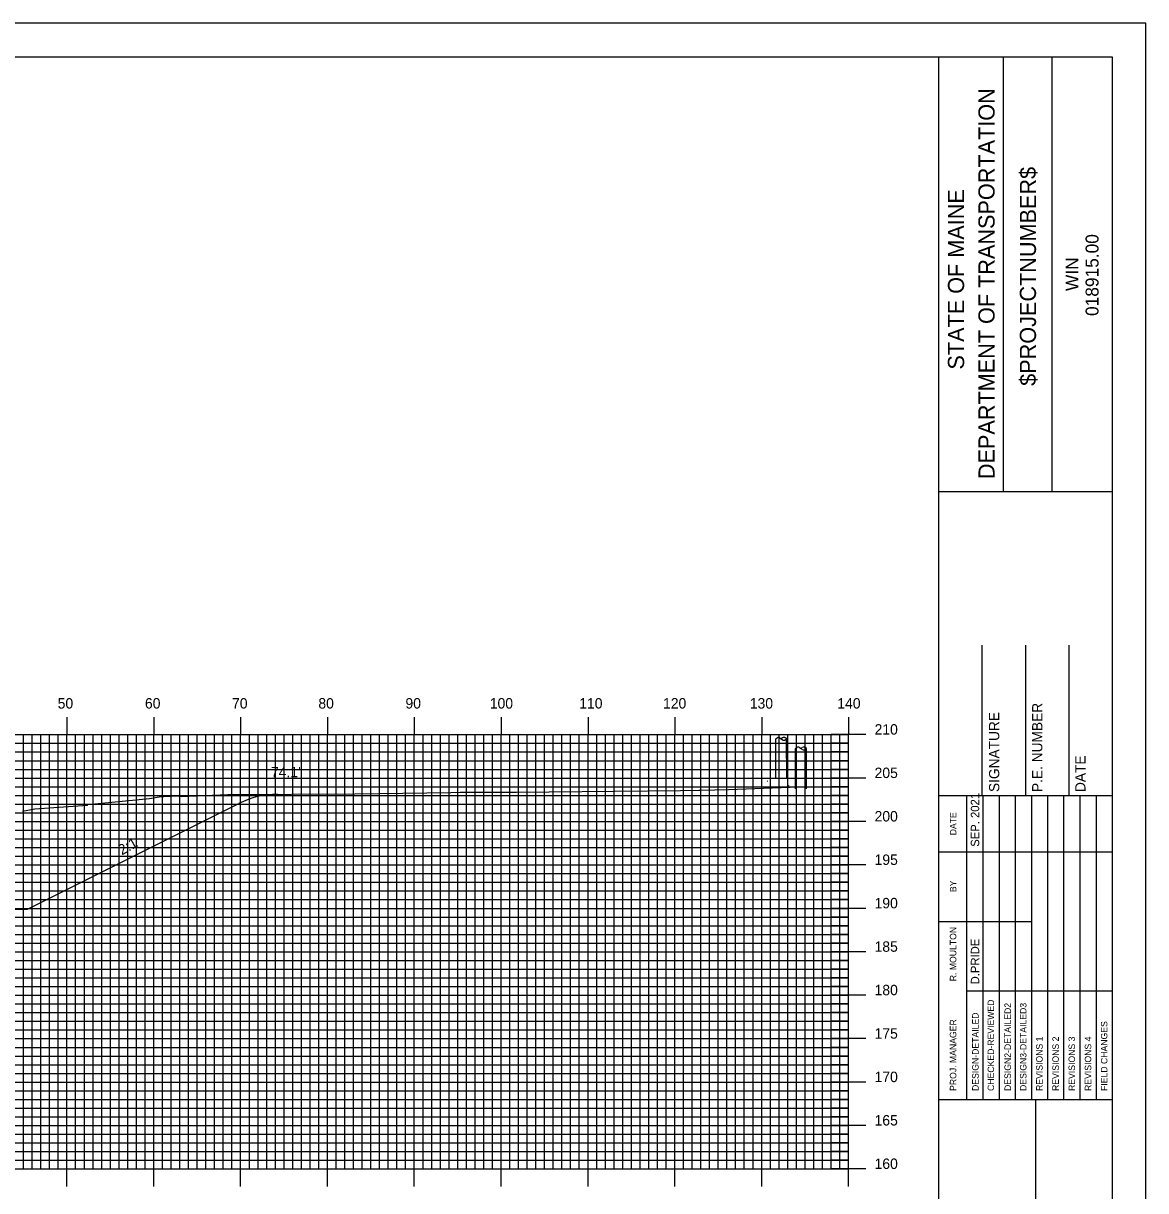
# Model space of a CAD drawing. Extents: x 1794846 to 1795189, y 442591 to 442811.
# Drawn here: x 1795056.8 to 1795186.1, y 442676.2 to 442810.5 of the extents above; entities that cross this region are included whole.
import ezdxf

# ---------------------------------------------------------------- set-up
doc = ezdxf.new("R2010")
doc.units = 0
for name, color, linetype in [('ANNOTATION', 7, 'Continuous'), ('BORDER', 7, 'Continuous'), ('D_Roadway_Centerline', 7, 'Continuous'), ('D_Text_Standard', 7, 'Continuous'), ('H_V ANNOTATION', 7, 'Continuous'), ('M_Utilities_Pole', 7, 'Continuous'), ('MAJOR', 7, 'Continuous'), ('MINOR', 7, 'Continuous'), ('PLOT BOUNDARY', 7, 'Continuous'), ('S_Roadway_Centerline', 7, 'Continuous'), ('S_Utilities_Pole_Power', 7, 'Continuous')]:
    doc.layers.add(name, color=color, linetype=linetype)

msp = doc.modelspace()

# ---------------------------------------------------------------- linework, layer by layer
at = {"layer": 'BORDER'}
for p, q in [((1795162.25, 442596.67), (1795162.25, 442806.67)), ((1795169.71, 442756.66), (1795169.71, 442806.66)), ((1795175.3, 442756.66), (1795175.3, 442806.66)), ((1795162.25, 442756.65), (1795182.25, 442756.65)), ((1795167.25, 442721.67), (1795167.25, 442738.97)), ((1795172.25, 442721.67), (1795172.25, 442738.97)), ((1795177.25, 442721.67), (1795177.25, 442738.97)), ((1795162.25, 442721.67), (1795182.25, 442721.67)), ((1795162.25, 442686.67), (1795182.25, 442686.67)), ((1795173.43, 442616.67), (1795173.43, 442686.67))]:
    msp.add_line(p, q, dxfattribs=at)
msp.add_lwpolyline([(1794862.25, 442596.67), (1795182.25, 442596.67), (1795182.25, 442806.67), (1794862.25, 442806.67)], close=True, dxfattribs=at)
for points in [[(1795165.48, 442715.17), (1795165.48, 442721.67)], [(1795167.35, 442686.68), (1795167.35, 442721.67)], [(1795169.21, 442721.67), (1795169.21, 442686.68)], [(1795171.07, 442686.68), (1795171.07, 442721.67)], [(1795172.94, 442686.68), (1795172.94, 442721.67)], [(1795174.8, 442686.68), (1795174.8, 442721.67)], [(1795176.66, 442686.68), (1795176.66, 442721.67)], [(1795178.53, 442686.68), (1795178.53, 442721.67)], [(1795180.39, 442686.68), (1795180.39, 442721.67)], [(1795165.48, 442686.68), (1795165.48, 442720.26)], [(1795162.25, 442715.17), (1795182.25, 442715.17)], [(1795162.25, 442707.17), (1795165.48, 442707.17)], [(1795165.48, 442707.17), (1795172.94, 442707.17)], [(1795165.48, 442699.17), (1795182.25, 442699.17)]]:
    msp.add_lwpolyline(points, dxfattribs=at)
at = {"layer": 'D_Roadway_Centerline'}
msp.add_lwpolyline([(1794974.71, 442699.87), (1794977.68, 442688), (1794981.68, 442689), (1794991.85, 442691.55), (1794999.85, 442691.87), (1795011.85, 442691.63), (1795023.85, 442691.39), (1795031.85, 442691.07), (1795042.03, 442688.52), (1795046.03, 442687.52), (1795051.29, 442708.57), (1795057.29, 442708.57), (1795081.65, 442720.74)], dxfattribs=at)
msp.add_arc((1795086.12, 442711.8), 10, 90.2277, 116.5651, dxfattribs=at)
at = {"layer": 'M_Utilities_Pole'}
for p, q in [((1795142.54, 442723.32), (1795142.54, 442723.3)), ((1795144.92, 442722.8), (1795144.92, 442722.78))]:
    msp.add_line(p, q, dxfattribs=at)
for centre in [(1795142.54, 442723.31), (1795144.92, 442722.79)]:
    msp.add_circle(centre, 0.00417, dxfattribs=at)
at = {"layer": 'MAJOR'}
for p, q in [((1795061.85, 442730.67), (1795061.85, 442728.67)), ((1795071.85, 442730.67), (1795071.85, 442728.67)), ((1795081.85, 442730.67), (1795081.85, 442728.67)), ((1795091.85, 442730.67), (1795091.85, 442728.67)), ((1795101.85, 442730.67), (1795101.85, 442728.67)), ((1795111.85, 442730.67), (1795111.85, 442728.67)), ((1795121.85, 442730.67), (1795121.85, 442728.67)), ((1795131.85, 442730.67), (1795131.85, 442728.67)), ((1795141.85, 442730.67), (1795141.85, 442728.67)), ((1795151.85, 442730.67), (1795151.85, 442728.67)), ((1794871.85, 442728.67), (1795151.85, 442728.67)), ((1794871.85, 442728.67), (1795151.85, 442728.67)), ((1795061.85, 442678.67), (1795061.85, 442728.67)), ((1795071.85, 442678.67), (1795071.85, 442728.67)), ((1795081.85, 442678.67), (1795081.85, 442728.67)), ((1795091.85, 442678.67), (1795091.85, 442728.67)), ((1795101.85, 442678.67), (1795101.85, 442728.67)), ((1795111.85, 442678.67), (1795111.85, 442728.67)), ((1795121.85, 442678.67), (1795121.85, 442728.67)), ((1795131.85, 442678.67), (1795131.85, 442728.67)), ((1795141.85, 442678.67), (1795141.85, 442728.67)), ((1795153.86, 442728.67), (1795149.85, 442728.67)), ((1795151.85, 442678.67), (1795151.85, 442728.67)), ((1795151.85, 442678.67), (1795151.85, 442728.67)), ((1794871.85, 442723.67), (1795151.85, 442723.67)), ((1795153.86, 442723.67), (1795149.85, 442723.67)), ((1794871.85, 442718.67), (1795151.85, 442718.67)), ((1795153.86, 442718.67), (1795149.85, 442718.67)), ((1794871.85, 442713.67), (1795151.85, 442713.67)), ((1795153.86, 442713.67), (1795149.85, 442713.67)), ((1794871.85, 442708.67), (1795151.85, 442708.67)), ((1795153.86, 442708.67), (1795149.85, 442708.67)), ((1794871.85, 442703.67), (1795151.85, 442703.67)), ((1795153.86, 442703.67), (1795149.85, 442703.67)), ((1794871.85, 442698.67), (1795151.85, 442698.67)), ((1795153.86, 442698.67), (1795149.85, 442698.67)), ((1794871.85, 442693.67), (1795151.85, 442693.67)), ((1795153.86, 442693.67), (1795149.85, 442693.67)), ((1794871.85, 442688.67), (1795151.85, 442688.67)), ((1795153.86, 442688.67), (1795149.85, 442688.67)), ((1794871.85, 442683.67), (1795151.85, 442683.67)), ((1795153.86, 442683.67), (1795149.85, 442683.67)), ((1794871.85, 442678.67), (1795151.85, 442678.67)), ((1794871.85, 442678.67), (1795151.85, 442678.67)), ((1795061.85, 442676.66), (1795061.85, 442678.67)), ((1795071.85, 442676.66), (1795071.85, 442678.67)), ((1795081.85, 442676.66), (1795081.85, 442678.67)), ((1795091.85, 442676.66), (1795091.85, 442678.67)), ((1795101.85, 442676.66), (1795101.85, 442678.67)), ((1795111.85, 442676.66), (1795111.85, 442678.67)), ((1795121.85, 442676.66), (1795121.85, 442678.67)), ((1795131.85, 442676.66), (1795131.85, 442678.67)), ((1795141.85, 442676.66), (1795141.85, 442678.67)), ((1795153.86, 442678.67), (1795149.85, 442678.67)), ((1795151.85, 442676.66), (1795151.85, 442678.67))]:
    msp.add_line(p, q, dxfattribs=at)
at = {"layer": 'MINOR'}
for p, q in [((1795056.85, 442678.67), (1795056.85, 442728.67)), ((1795057.85, 442678.67), (1795057.85, 442728.67)), ((1795058.85, 442678.67), (1795058.85, 442728.67)), ((1795059.85, 442678.67), (1795059.85, 442728.67)), ((1795060.85, 442678.67), (1795060.85, 442728.67)), ((1795062.85, 442678.67), (1795062.85, 442728.67)), ((1795063.85, 442678.67), (1795063.85, 442728.67)), ((1795064.85, 442678.67), (1795064.85, 442728.67)), ((1795065.85, 442678.67), (1795065.85, 442728.67)), ((1795066.85, 442678.67), (1795066.85, 442728.67)), ((1795067.85, 442678.67), (1795067.85, 442728.67)), ((1795068.85, 442678.67), (1795068.85, 442728.67)), ((1795069.85, 442678.67), (1795069.85, 442728.67)), ((1795070.85, 442678.67), (1795070.85, 442728.67)), ((1795072.85, 442678.67), (1795072.85, 442728.67)), ((1795073.85, 442678.67), (1795073.85, 442728.67)), ((1795074.85, 442678.67), (1795074.85, 442728.67)), ((1795075.85, 442678.67), (1795075.85, 442728.67)), ((1795076.85, 442678.67), (1795076.85, 442728.67)), ((1795077.85, 442678.67), (1795077.85, 442728.67)), ((1795078.85, 442678.67), (1795078.85, 442728.67)), ((1795079.85, 442678.67), (1795079.85, 442728.67)), ((1795080.85, 442678.67), (1795080.85, 442728.67)), ((1795082.85, 442678.67), (1795082.85, 442728.67)), ((1795083.85, 442678.67), (1795083.85, 442728.67)), ((1795084.85, 442678.67), (1795084.85, 442728.67)), ((1795085.85, 442678.67), (1795085.85, 442728.67)), ((1795086.85, 442678.67), (1795086.85, 442728.67)), ((1795087.85, 442678.67), (1795087.85, 442728.67)), ((1795088.85, 442678.67), (1795088.85, 442728.67)), ((1795089.85, 442678.67), (1795089.85, 442728.67)), ((1795090.85, 442678.67), (1795090.85, 442728.67)), ((1795092.85, 442678.67), (1795092.85, 442728.67)), ((1795093.85, 442678.67), (1795093.85, 442728.67)), ((1795094.85, 442678.67), (1795094.85, 442728.67)), ((1795095.85, 442678.67), (1795095.85, 442728.67)), ((1795096.85, 442678.67), (1795096.85, 442728.67)), ((1795097.85, 442678.67), (1795097.85, 442728.67)), ((1795098.85, 442678.67), (1795098.85, 442728.67)), ((1795099.85, 442678.67), (1795099.85, 442728.67)), ((1795100.85, 442678.67), (1795100.85, 442728.67)), ((1795102.85, 442678.67), (1795102.85, 442728.67)), ((1795103.85, 442678.67), (1795103.85, 442728.67)), ((1795104.85, 442678.67), (1795104.85, 442728.67)), ((1795105.85, 442678.67), (1795105.85, 442728.67)), ((1795106.85, 442678.67), (1795106.85, 442728.67)), ((1795107.85, 442678.67), (1795107.85, 442728.67)), ((1795108.85, 442678.67), (1795108.85, 442728.67)), ((1795109.85, 442678.67), (1795109.85, 442728.67)), ((1795110.85, 442678.67), (1795110.85, 442728.67)), ((1795112.85, 442678.67), (1795112.85, 442728.67)), ((1795113.85, 442678.67), (1795113.85, 442728.67)), ((1795114.85, 442678.67), (1795114.85, 442728.67)), ((1795115.85, 442678.67), (1795115.85, 442728.67)), ((1795116.85, 442678.67), (1795116.85, 442728.67)), ((1795117.85, 442678.67), (1795117.85, 442728.67)), ((1795118.85, 442678.67), (1795118.85, 442728.67)), ((1795119.85, 442678.67), (1795119.85, 442728.67)), ((1795120.85, 442678.67), (1795120.85, 442728.67)), ((1795122.85, 442678.67), (1795122.85, 442728.67)), ((1795123.85, 442678.67), (1795123.85, 442728.67)), ((1795124.85, 442678.67), (1795124.85, 442728.67)), ((1795125.85, 442678.67), (1795125.85, 442728.67)), ((1795126.85, 442678.67), (1795126.85, 442728.67)), ((1795127.85, 442678.67), (1795127.85, 442728.67)), ((1795128.85, 442678.67), (1795128.85, 442728.67)), ((1795129.85, 442678.67), (1795129.85, 442728.67)), ((1795130.85, 442678.67), (1795130.85, 442728.67)), ((1795132.85, 442678.67), (1795132.85, 442728.67)), ((1795133.85, 442678.67), (1795133.85, 442728.67)), ((1795134.85, 442678.67), (1795134.85, 442728.67)), ((1795135.85, 442678.67), (1795135.85, 442728.67)), ((1795136.85, 442678.67), (1795136.85, 442728.67)), ((1795137.85, 442678.67), (1795137.85, 442728.67)), ((1795138.85, 442678.67), (1795138.85, 442728.67)), ((1795139.85, 442678.67), (1795139.85, 442728.67)), ((1795140.85, 442678.67), (1795140.85, 442728.67)), ((1795142.85, 442678.67), (1795142.85, 442728.67)), ((1795143.85, 442678.67), (1795143.85, 442728.67)), ((1795144.85, 442678.67), (1795144.85, 442728.67)), ((1795145.85, 442678.67), (1795145.85, 442728.67)), ((1795146.85, 442678.67), (1795146.85, 442728.67)), ((1795147.85, 442678.67), (1795147.85, 442728.67)), ((1795148.85, 442678.67), (1795148.85, 442728.67)), ((1795149.85, 442678.67), (1795149.85, 442728.67)), ((1795150.85, 442678.67), (1795150.85, 442728.67)), ((1794871.85, 442727.67), (1795151.85, 442727.67)), ((1795151.85, 442727.67), (1795149.85, 442727.67)), ((1794871.85, 442726.67), (1795151.85, 442726.67)), ((1795151.85, 442726.67), (1795149.85, 442726.67)), ((1794871.85, 442725.67), (1795151.85, 442725.67)), ((1794871.85, 442724.67), (1795151.85, 442724.67)), ((1795151.85, 442725.67), (1795149.85, 442725.67)), ((1795151.85, 442724.67), (1795149.85, 442724.67)), ((1794871.85, 442722.67), (1795151.85, 442722.67)), ((1795151.85, 442722.67), (1795149.85, 442722.67)), ((1794871.85, 442721.67), (1795151.85, 442721.67)), ((1794871.85, 442720.67), (1795151.85, 442720.67)), ((1795151.85, 442721.67), (1795149.85, 442721.67)), ((1795151.85, 442720.67), (1795149.85, 442720.67)), ((1794871.85, 442719.67), (1795151.85, 442719.67)), ((1795151.85, 442719.67), (1795149.85, 442719.67)), ((1794871.85, 442717.67), (1795151.85, 442717.67)), ((1794871.85, 442716.67), (1795151.85, 442716.67)), ((1795151.85, 442717.67), (1795149.85, 442717.67)), ((1795151.85, 442716.67), (1795149.85, 442716.67)), ((1794871.85, 442715.67), (1795151.85, 442715.67)), ((1795151.85, 442715.67), (1795149.85, 442715.67)), ((1794871.85, 442714.67), (1795151.85, 442714.67)), ((1795151.85, 442714.67), (1795149.85, 442714.67)), ((1794871.85, 442712.67), (1795151.85, 442712.67)), ((1795151.85, 442712.67), (1795149.85, 442712.67)), ((1794871.85, 442711.67), (1795151.85, 442711.67)), ((1795151.85, 442711.67), (1795149.85, 442711.67)), ((1794871.85, 442710.67), (1795151.85, 442710.67)), ((1795151.85, 442710.67), (1795149.85, 442710.67)), ((1794871.85, 442709.67), (1795151.85, 442709.67)), ((1795151.85, 442709.67), (1795149.85, 442709.67)), ((1794871.85, 442707.67), (1795151.85, 442707.67)), ((1795151.85, 442707.67), (1795149.85, 442707.67)), ((1794871.85, 442706.67), (1795151.85, 442706.67)), ((1795151.85, 442706.67), (1795149.85, 442706.67)), ((1794871.85, 442705.67), (1795151.85, 442705.67)), ((1794871.85, 442704.67), (1795151.85, 442704.67)), ((1795151.85, 442705.67), (1795149.85, 442705.67)), ((1795151.85, 442704.67), (1795149.85, 442704.67)), ((1794871.85, 442702.67), (1795151.85, 442702.67)), ((1795151.85, 442702.67), (1795149.85, 442702.67)), ((1794871.85, 442701.67), (1795151.85, 442701.67)), ((1794871.85, 442700.67), (1795151.85, 442700.67)), ((1795151.85, 442701.67), (1795149.85, 442701.67)), ((1795151.85, 442700.67), (1795149.85, 442700.67)), ((1794871.85, 442699.67), (1795151.85, 442699.67)), ((1795151.85, 442699.67), (1795149.85, 442699.67)), ((1794871.85, 442697.67), (1795151.85, 442697.67)), ((1794871.85, 442696.67), (1795151.85, 442696.67)), ((1795151.85, 442697.67), (1795149.85, 442697.67)), ((1795151.85, 442696.67), (1795149.85, 442696.67)), ((1794871.85, 442695.67), (1795151.85, 442695.67)), ((1795151.85, 442695.67), (1795149.85, 442695.67)), ((1794871.85, 442694.67), (1795151.85, 442694.67)), ((1795151.85, 442694.67), (1795149.85, 442694.67)), ((1794871.85, 442692.67), (1795151.85, 442692.67)), ((1795151.85, 442692.67), (1795149.85, 442692.67)), ((1794871.85, 442691.67), (1795151.85, 442691.67)), ((1795151.85, 442691.67), (1795149.85, 442691.67)), ((1794871.85, 442690.67), (1795151.85, 442690.67)), ((1794871.85, 442689.67), (1795151.85, 442689.67)), ((1795151.85, 442690.67), (1795149.85, 442690.67)), ((1795151.85, 442689.67), (1795149.85, 442689.67)), ((1794871.85, 442687.67), (1795151.85, 442687.67)), ((1795151.85, 442687.67), (1795149.85, 442687.67)), ((1794871.85, 442686.67), (1795151.85, 442686.67)), ((1794871.85, 442685.67), (1795151.85, 442685.67)), ((1795151.85, 442686.67), (1795149.85, 442686.67)), ((1795151.85, 442685.67), (1795149.85, 442685.67)), ((1794871.85, 442684.67), (1795151.85, 442684.67)), ((1795151.85, 442684.67), (1795149.85, 442684.67)), ((1794871.85, 442682.67), (1795151.85, 442682.67)), ((1794871.85, 442681.67), (1795151.85, 442681.67)), ((1795151.85, 442682.67), (1795149.85, 442682.67)), ((1795151.85, 442681.67), (1795149.85, 442681.67)), ((1794871.85, 442680.67), (1795151.85, 442680.67)), ((1795151.85, 442680.67), (1795149.85, 442680.67)), ((1794871.85, 442679.67), (1795151.85, 442679.67)), ((1795151.85, 442679.67), (1795149.85, 442679.67))]:
    msp.add_line(p, q, dxfattribs=at)
at = {"layer": 'PLOT BOUNDARY'}
msp.add_lwpolyline([(1794846.07, 442590.55), (1795186.07, 442590.55), (1795186.07, 442810.55), (1794846.07, 442810.55)], close=True, dxfattribs=at)
at = {"layer": 'S_Roadway_Centerline'}
msp.add_lwpolyline([(1795056.72, 442719.86), (1795058.16, 442720.13), (1795064.22, 442720.56), (1795064.25, 442720.63), (1795071.34, 442721.33), (1795072.71, 442721.56), (1795073.02, 442721.54), (1795074.7, 442721.61), (1795074.99, 442721.54), (1795080.36, 442721.78), (1795095, 442721.84), (1795106.05, 442721.99), (1795107.12, 442722.06), (1795113.63, 442722.04), (1795117.37, 442722.09), (1795132.49, 442722.24), (1795134.63, 442722.27), (1795134.87, 442722.26), (1795138.02, 442722.37), (1795145.1, 442722.63), (1795145.14, 442722.63), (1795148.88, 442722.65), (1795151.29, 442722.68), (1795151.85, 442722.68)], dxfattribs=at)
at = {"layer": 'S_Utilities_Pole_Power'}
for p, q in [((1795143.48, 442723.56), (1795143.47, 442728.18)), ((1795143.48, 442728.18), (1795143.63, 442728.29)), ((1795143.95, 442728.29), (1795144.1, 442728.18)), ((1795144.26, 442728.29), (1795144.1, 442728.18)), ((1795144.1, 442728.18), (1795144.26, 442728.07)), ((1795144.73, 442728.18), (1795144.57, 442728.29)), ((1795144.57, 442728.07), (1795144.73, 442728.18)), ((1795144.73, 442723.56), (1795144.72, 442728.18)), ((1795145.75, 442727.06), (1795145.91, 442727.17)), ((1795145.75, 442722.44), (1795145.75, 442727.06)), ((1795146.22, 442727.17), (1795146.38, 442727.06)), ((1795146.53, 442727.17), (1795146.38, 442727.06)), ((1795146.38, 442727.06), (1795146.53, 442726.95)), ((1795147, 442727.06), (1795146.85, 442727.17)), ((1795146.85, 442726.95), (1795147, 442727.06)), ((1795147, 442722.44), (1795147, 442727.06))]:
    msp.add_line(p, q, dxfattribs=at)
for centre, start, end in [((1795143.79, 442728.07), 90, 125.2644), ((1795143.79, 442728.07), 54.7356, 90), ((1795144.42, 442728.07), 90, 125.2644), ((1795144.42, 442728.29), 234.7356, 270), ((1795144.42, 442728.07), 54.7356, 90), ((1795144.42, 442728.29), 270, 305.2644), ((1795146.06, 442726.95), 90, 125.2644), ((1795146.06, 442726.95), 54.7356, 90), ((1795146.69, 442726.95), 90, 125.2644), ((1795146.69, 442727.17), 234.7356, 270), ((1795146.69, 442726.95), 54.7356, 90), ((1795146.69, 442727.17), 270, 305.2644)]:
    msp.add_arc(centre, 0.271, start, end, dxfattribs=at)

# ---------------------------------------------------------------- texts
at = {"layer": 'ANNOTATION'}
msp.add_text('2:1', height=1.2, rotation=29.7449, dxfattribs=at).set_placement((1795068.18, 442714.76))
at = {"layer": 'BORDER'}
for s, height, p in [('DEPARTMENT OF TRANSPORTATION', 1.8635, (1795168.67, 442758.08)), ('$PROJECTNUMBER$', 1.8635, (1795173.44, 442768.82)), ('STATE OF MAINE', 1.8635, (1795165.16, 442770.69)), ('018915.00', 1.491, (1795180.64, 442776.86)), ('WIN', 1.491, (1795178.33, 442779.73)), ('P.E. NUMBER', 1.1811, (1795174.17, 442722.06)), ('SIGNATURE', 1.181, (1795169.21, 442722.06)), ('DATE', 1.181, (1795179.14, 442722.06)), ('SEP. 2021', 0.969, (1795166.9, 442715.76)), ('DATE', 0.743, (1795164.26, 442717.08)), ('BY', 0.743, (1795164.26, 442710.54)), ('R. MOULTON', 0.745, (1795164.26, 442700.28)), ('D.PRIDE', 0.969, (1795166.9, 442699.92)), ('CHECKED-REVIEWED', 0.7455, (1795168.61, 442687.65)), ('DESIGN2-DETAILED2', 0.7455, (1795170.55, 442687.65)), ('DESIGN3-DETAILED3', 0.7455, (1795172.34, 442687.65)), ('DESIGN-DETAILED', 0.7455, (1795166.83, 442687.65)), ('PROJ. MANAGER', 0.7455, (1795164.26, 442687.65)), ('FIELD CHANGES', 0.7455, (1795181.66, 442687.65)), ('REVISIONS 1', 0.7455, (1795174.2, 442687.65)), ('REVISIONS 2', 0.7455, (1795176.07, 442687.65)), ('REVISIONS 3', 0.7455, (1795177.93, 442687.65)), ('REVISIONS 4', 0.7455, (1795179.8, 442687.65))]:
    msp.add_text(s, height=height, rotation=90, dxfattribs=at).set_placement(p)
at = {"layer": 'D_Text_Standard'}
msp.add_text("74.1'", height=1.2, dxfattribs=at).set_placement((1795085.35, 442723.76))
at = {"layer": 'H_V ANNOTATION'}
for s, p in [('50', (1795060.78, 442731.67)), ('60', (1795070.83, 442731.67)), ('70', (1795080.86, 442731.67)), ('80', (1795090.8, 442731.67)), ('90', (1795100.83, 442731.67)), ('100', (1795110.54, 442731.67)), ('110', (1795120.84, 442731.67)), ('120', (1795130.49, 442731.67)), ('130', (1795140.48, 442731.67)), ('140', (1795150.56, 442731.67)), ('210', (1795154.85, 442728.67)), ('205', (1795154.85, 442723.67)), ('200', (1795154.85, 442718.67)), ('195', (1795154.85, 442713.67)), ('190', (1795154.85, 442708.67)), ('185', (1795154.85, 442703.67)), ('180', (1795154.85, 442698.67)), ('175', (1795154.85, 442693.67)), ('170', (1795154.85, 442688.67)), ('165', (1795154.85, 442683.67)), ('160', (1795154.85, 442678.67))]:
    msp.add_text(s, height=1.2, dxfattribs=at).set_placement(p)

doc.saveas('drawing.dxf')
